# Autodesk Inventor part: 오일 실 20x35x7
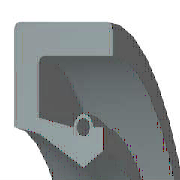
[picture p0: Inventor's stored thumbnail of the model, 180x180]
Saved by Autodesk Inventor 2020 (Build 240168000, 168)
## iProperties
IsCustomPart: 1
Created: 2012-02
Part Number: 오일 실 20x35x7
Material: 고무
Description: 회전 샤프트 립 유형 실 2 - 금속 케이스
Document SubType Name: Modeling
Standard: ISO 6194/1
Designer: mduedu
Standards Organization: ISO
Language: ko-KR
Size Designation: 20x35x7-유형 2
Categories: <MemberInstance><Categories><Category DisplayName="샤프트 부품" InternalName="7f7aeb1f-a693-4053-b835-cee3144e0d98" Mnemonic="SHFT"><Category DisplayName="실링" Intern
Density: 0.93 g/cm^3
Appearance: 고무 - 검은색 - 버전 1.1
Author: mduedu
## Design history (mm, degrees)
node "WorkPlane2"
node "WorkPoint1"
node "WorkPlane3"
body "Solid1"
node "스케치1"
revolve "회전1" stored, may be unused: angle "d37" = 360 deg
fillet "모깎기1" dims "d38" = 0.35 (= 0.05 x b)
sketch "스케치2"
  geometry: L1 (16, -0.35)-(16.8, -0.35); L2 (16, 0)-(16, -0.35); L3 (17.5, 0)-(16, 0); L4 (17.5, -7)-(17.5, 0); L5 (12.22, -7)-(17.5, -7); L6 (11.283, -4.2)-(12.22, -7); L7 (10.601, -3.72)-(11.283, -4.2); L8 (10, -1.925)-(10.601, -3.72); L9 (10.789, -1.05)-(10, -1.925); L10 (12.664, -1.05)-(10.789, -1.05); L11 (12.664, -1.925)-(12.664, -1.05); L12 (12.664, -5.6)-(12.664, -3.325); L13 (13.664, -5.6)-(12.664, -5.6); L14 (13.664, -6.3)-(13.664, -5.6); L15 (16.8, -6.3)-(13.664, -6.3); L16 (16.8, -0.35)-(16.8, -6.3); L17 (0, -15.959)-(0, 2.029); L18 (0, -15.959)-(0, 2.029); L19 (0, -19.557)-(0, 5.626) reference; L20 (-5.2, 0)-(31.2, 0) reference; A1 r 0.7 centre (12.664, -2.625) between (12.664, -3.325) and (12.664, -1.925)
  constraints: 36 end point, 7 vertical, 6 horizontal, 2 collinear, 2 point on circle, 1 centre point, 1 parallel, 1 point on line
  dimensions: "d2" = 0.35 distance of L2.start L1.start (= 0.05 x b); "d4" = 7 distance of L4.start L3.start (= b); "d6" = 0.7 horizontal distance of L1.end L3.start (= 0.1 x b); "d8" = 0.7 horizontal distance of L15.start L4.start (= 0.1 x b); "d10" = 0.7 distance of L14.start L13.start (= 0.1 x b); "d12" = 0.7 vertical distance of L1.end L10.start (= 0.1 x b); "d14" = 0.875 distance of L11.start L10.start (= 0.125 x b); "d16" = 0.7 radius of A1 (= 0.1 x b); "d18" = 0 horizontal distance of A1.centre L12.end; "d20" = 0.875 vertical distance of L9.start L8.start (= 0.125 x b); "d22" = 1.79487 vertical distance of L8.start L7.start (= 0.25641 x b); "d24" = 2.8 vertical distance of L6.start L5.start (= 0.4 x b); "d26" = 1.5 distance of L3.start L2.start (= 0.1 x dd - 0.1 x Diam); "d28" = 0.78947 horizontal distance of L9.start L8.start (= 0.0526316 x dd - 0.0526316 x Diam); "d30" = 1.875 distance of L10.start L9.start (= 0.125 x dd - 0.125 x Diam); "d32" = 1 distance of L13.start L12.start (= 0.0666667 x dd - 0.0666667 x Diam); "d34" = 0.9375 horizontal distance of L6.start L5.start (= 0.0625 x dd - 0.0625 x Diam); "d36" = 0.68182 horizontal distance of L7.start L6.start (= 0.0454545 x dd - 0.0454545 x Diam); "msp_d39" = 20 diameter of L8.start L17 (= Diam); "msp_d40" = 35 diameter of L4 L17 (= dd)
other parameters: "dd" = 35 [user parameter; used in 7 equation terms], "Diam" = 20 [user parameter; used in 7 equation terms], "b" = 7 [user parameter; used in 13 equation terms], "d0" = -7 (computed from b), "d1" = 0.4 (derived), "d3" = 8 (derived), "d5" = 0.8 (derived), "d7" = 0.8 (derived), "d9" = 0.8 (derived), "d11" = 0.8 (derived), "d13" = 1 (derived), "d15" = 0.8 (derived), "d17" = 0 (derived), "d19" = 1 (derived), "d21" = 2.05128 (derived), "d23" = 3.2 (derived), "d25" = 2 (derived), "d27" = 1.05263 (derived), "d29" = 2.5 (derived), "d31" = 1.33333 (derived), "d33" = 1.25 (derived), "d35" = 0.90909 (derived), "d42" = 0
